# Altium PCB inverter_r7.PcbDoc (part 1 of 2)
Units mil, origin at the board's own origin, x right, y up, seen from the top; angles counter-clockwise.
Board outline 7000 x 5200 mil, 2 copper layers (Top Layer, Bottom Layer), stack 92.8 mil thick; 90 components, 75 nets, 259 pads, 1172 vias.
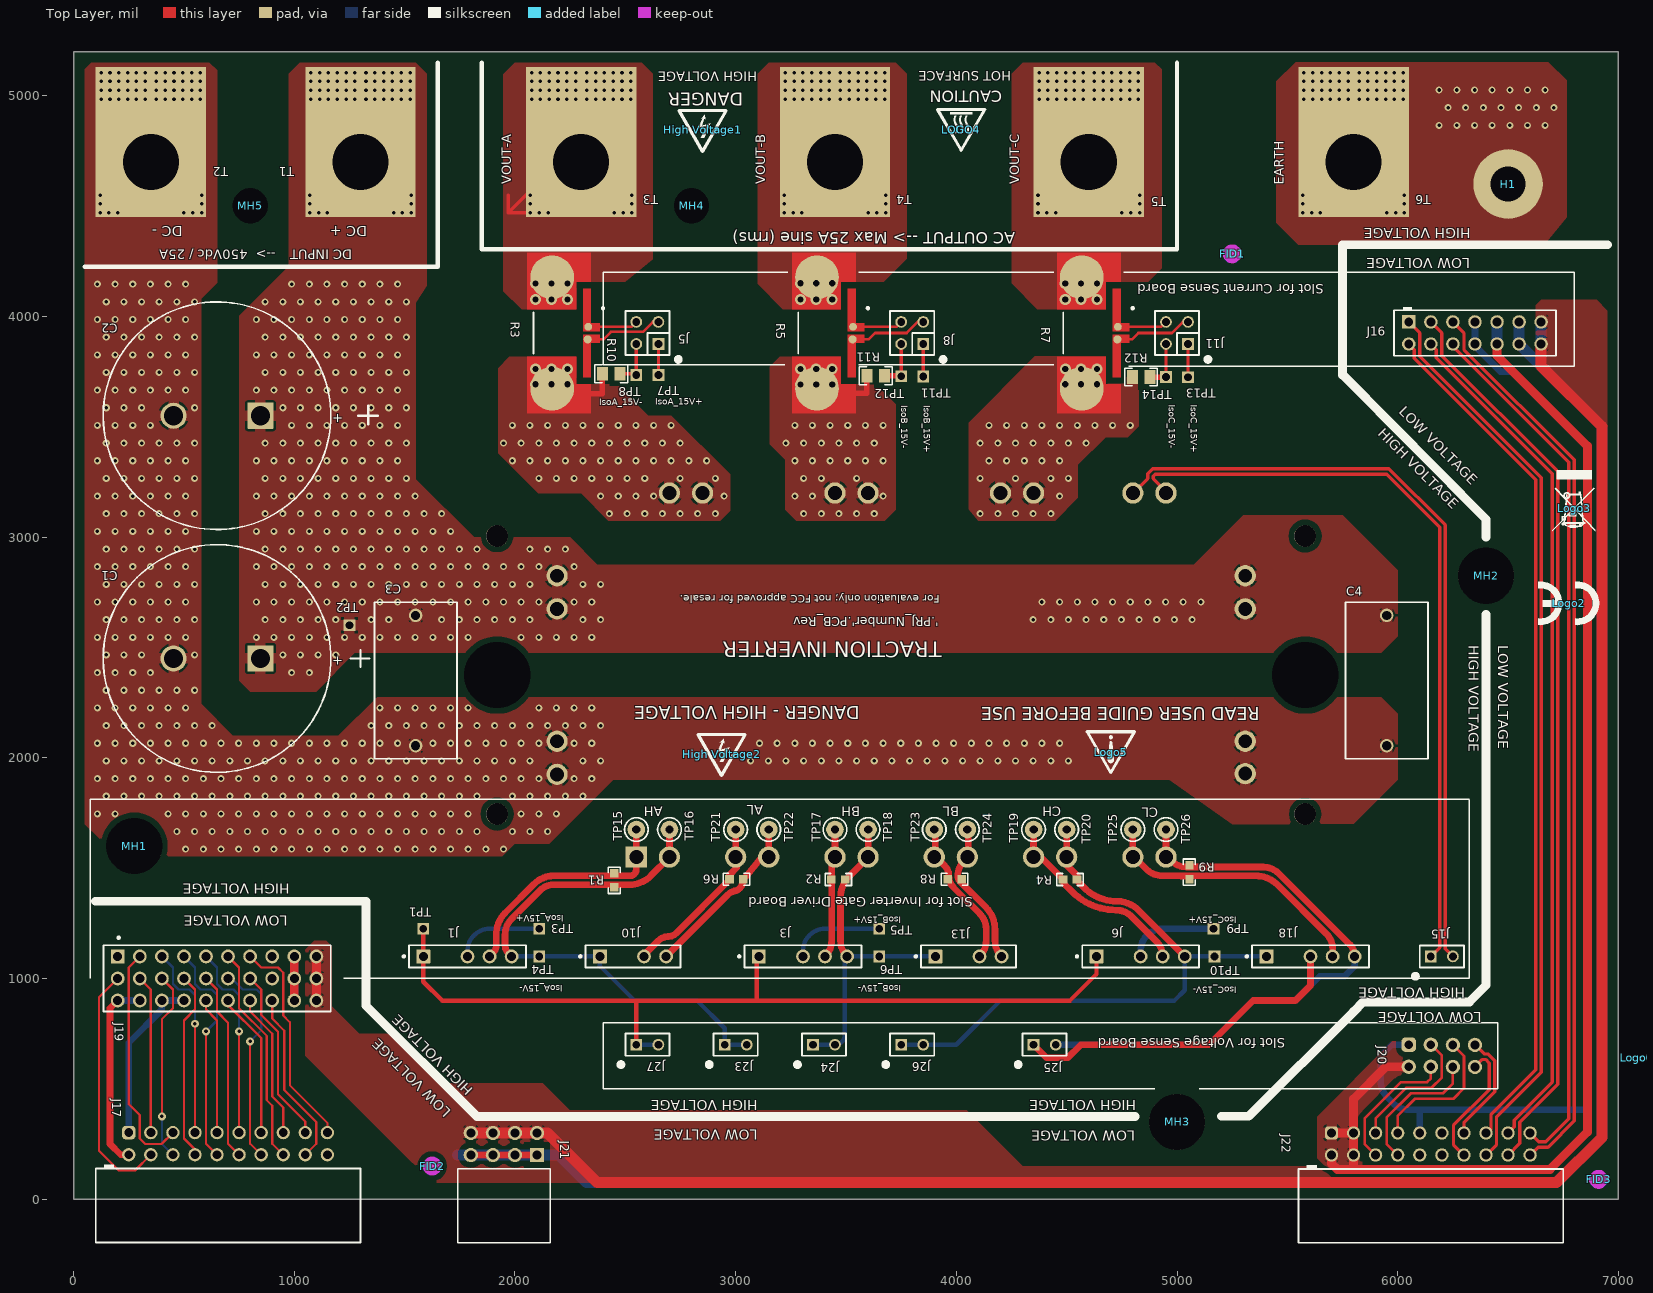
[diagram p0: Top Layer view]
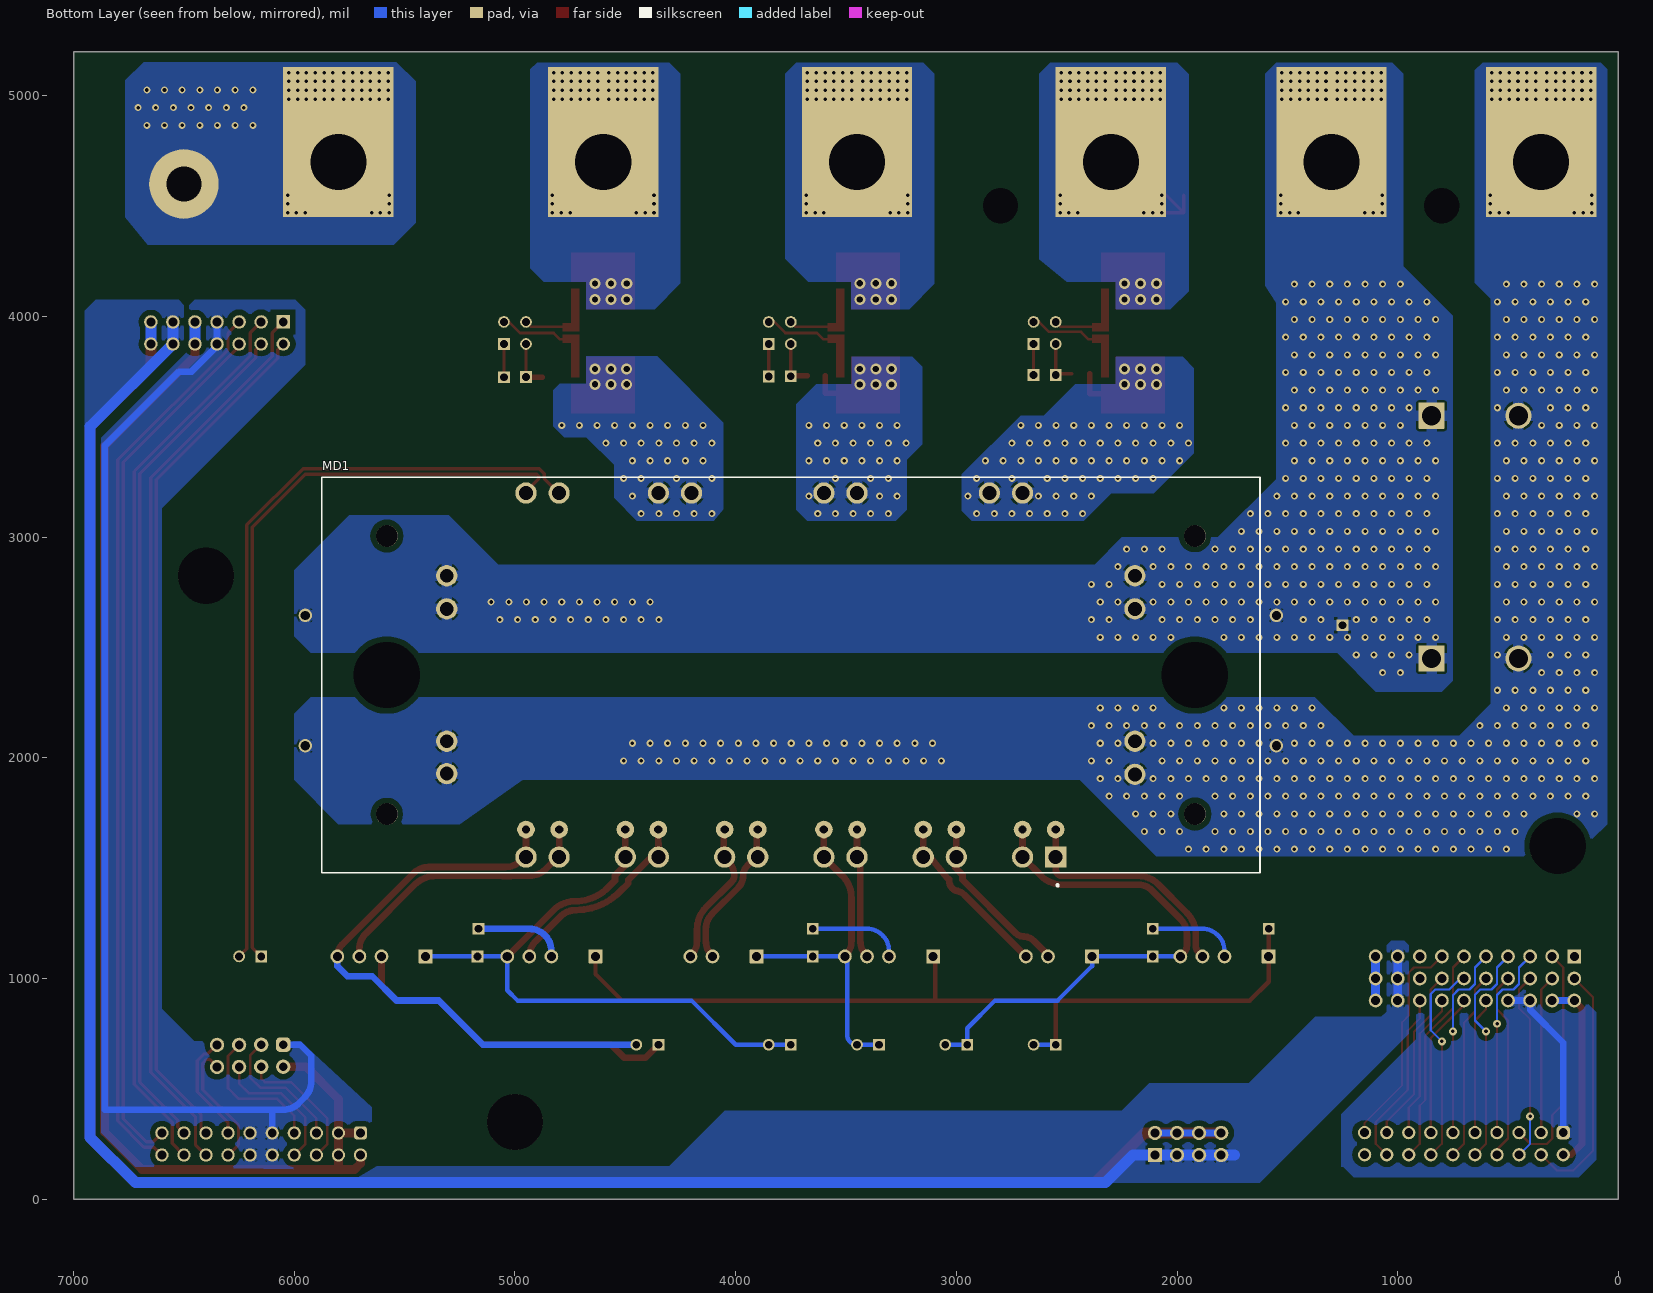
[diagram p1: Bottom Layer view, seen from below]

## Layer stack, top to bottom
Top Solder: solder mask 0.4, Solder Resist, Dk 3.5
Top Layer: signal copper 2.8
Dielectric1: core 87.2, FR-4, Dk 4.8
Bottom Layer: signal copper 2.8
Bottom Solder: solder mask 0.4, Solder Resist, Dk 3.5

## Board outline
0,0 7000,0 7000,5200 0,5200

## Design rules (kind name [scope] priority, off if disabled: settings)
AcuteAngle [All] p1: minimum=4.50000000000000E+0001 checktracksonly=FALSE
AssemblyTestPointUsage [All] p1: valid=2
BoardOutlineClearance BoardOutlineClearance_MountingHoles [OnCopper and InComponentClass('Mounting Holes')] p1: gap=39.37 ignorepadtopadclearanceinfootprint=FALSE
BoardOutlineClearance BoardOutlineClearance_Poly [OnCopper and IsPoly] p2: gap=25 ignorepadtopadclearanceinfootprint=FALSE
BoardOutlineClearance [OnCopper and Not InComponentClass('Logo') and not InComponentClass('FiducialMark') and not InRegion(1000,500,4000,800) and not InPoly] p3: gap=50 ignorepadtopadclearanceinfootprint=FALSE
Clearance Clearance_Keepouts [((IsTrack Or IsArc) And Not InPoly) And IsFree and IsKeepOut vs ((IsTrack Or IsArc) And Not InPoly) And IsFree and IsKeepOut] p1: gap=0 ignorepadtopadclearanceinfootprint=FALSE
Clearance Clearance_Poly [InPolygon] p2: gap=25 ignorepadtopadclearanceinfootprint=TRUE
Clearance Clearance_FiducialMark [IsKeepOut and InComponentClass('FiducialMark') vs IsPad and InComponentClass('FiducialMark')] p3: gap=0 ignorepadtopadclearanceinfootprint=FALSE
Clearance [All] p4: gap=10 ignorepadtopadclearanceinfootprint=TRUE
ComponentClearance ComponentClearance_MountingHoles_FiducialMarks [InComponentClass('Mounting Holes') vs InComponentClass('FiducialMark')] p1: gap=50 collisioncheckmode=3 verticalgap=10 showdistances=FALSE
ComponentClearance ComponentClearance_Shunt [InComponentClass('Header') vs InComponentClass('Shunt')] p2: gap=0 collisioncheckmode=3 verticalgap=0 showdistances=FALSE
ComponentClearance ComponentClearance_Logo [InComponentClass('Logo')] p3: gap=50 collisioncheckmode=3 verticalgap=10 showdistances=FALSE
ComponentClearance ComponentClearance_ScrewToNut [(HasFootprint('NY PMS 440 0025 PH')) vs (HasFootprint('Keystone_1902C'))] p4: gap=5 collisioncheckmode=3 verticalgap=10 showdistances=FALSE
ComponentClearance ComponentClearance_MountingHoles [InComponentClass('Mounting Holes')] p5: gap=250 collisioncheckmode=3 verticalgap=100000 showdistances=FALSE
ComponentClearance ComponentClearance_SmallPassives [HasFootprint('0201*') or HasFootprint('0402*') or HasFootprint('0508') or HasFootprint('0603*') or HasFootprint('0612') or HasFootprint('0805*') or HasFootprint('0815*') or HasFootprint('0830*') or HasFootprint('1206*') or HasFootprint('1210*') or HasFootprint('1808*') or HasFootprint('1812*') or HasFootprint('1825*') or HasFootprint('2010*') or HasFootprint('2220*') or HasFootprint('2225*') or HasFootprint('2512*') or HasFootprint('2728*') or HasFootprint('3518*') vs HasFootprint('0201*') or HasFootprint('0402*') or HasFootprint('0508') or HasFootprint('0603*') or HasFootprint('0612') or HasFootprint('0805*') or HasFootprint('0815*') or HasFootprint('0830*') or HasFootprint('1206*') or HasFootprint('1210*') or HasFootprint('1808*') or HasFootprint('1812*') or HasFootprint('1825*') or HasFootprint('2010*') or HasFootprint('2220*') or HasFootprint('2225*') or HasFootprint('2512*') or HasFootprint('2728*') or HasFootprint('3518*')] p6: gap=14.96 collisioncheckmode=3 verticalgap=10 showdistances=FALSE
ComponentClearance ComponentClearance_THtoSMT [IsThruComponent vs IsSMTComponent] p7: gap=40 collisioncheckmode=3 verticalgap=30 showdistances=FALSE
ComponentClearance ComponentClearance_THtoTH [IsThruComponent vs IsThruComponent] p8: gap=30 collisioncheckmode=3 verticalgap=30 showdistances=FALSE
ComponentClearance [All] p9: gap=30 collisioncheckmode=3 verticalgap=10 showdistances=FALSE
DiffPairsRouting [All] p1: maxlimit=100 minlimit=10 mostfreqgap=10 toplayer_minwidth=15 toplayer_maxwidth=30 toplayer_prefwidth=15 bottomlayer_minwidth=15 bottomlayer_maxwidth=30 bottomlayer_prefwidth=15 maxuncoupledlength=1000
FabricationTestPointUsage TestPointUsage [All] p1: valid=2 allowmultiple=FALSE
FabricationTestpoint Testpoint [All] p1: side=3 testpointundercomponent=TRUE minsize=40 maxsize=100 preferedsize=60 minholesize=0 maxholesize=40 preferedholesize=32 testpointgrid=1 allowsidetop=TRUE allowsidebottom=TRUE usegrid=TRUE gridtolerance=0.01
FanoutControl Fanout_LCC [IsLCC] p1: bgadir=Out bgaviamode=Centered fanoutstyle=Auto fanoutdirection=Alternating viagrid=1 // Fanout_LCC (Default Rule)
FanoutControl Fanout_BGA [IsBGA] p2: bgadir=Out bgaviamode=Centered fanoutstyle=Auto fanoutdirection=Alternating viagrid=1 // Fanout_BGA (Default Rule)
FanoutControl Fanout_Default [All] p4: bgadir=Out bgaviamode=Centered fanoutstyle=Auto fanoutdirection=Alternating viagrid=1 // Fanout_Default (Default Rule)
FanoutControl Fanout_Small [(CompPinCount < 5)] p5: bgadir=Out bgaviamode=Centered fanoutstyle=Auto fanoutdirection=OutThenIn viagrid=1 // Fanout_Small (Default Rule)
Height [All] p1: minheight=0 maxheight=2000 prefheight=500
HoleSize [All] p1: absolutevalues=TRUE maxlimit=320 minlimit=7.87 maxpercent=80.000 minpercent=20.000
MinimumAnnularRing MinimumAnnularRing_ThermalPadVias [IsVia and InAnyComponent] p1: minimumring=5.91
MinimumAnnularRing [All] p2: minimumring=7.87
MinimumSolderMaskSliver MinimumSolderMaskSliver_Logo [InComponentClass('Logo') vs InComponentClass('Logo')] p1: minsoldermaskwidth=0.7
MinimumSolderMaskSliver [All] p2: minsoldermaskwidth=3.94
PlaneConnect [All] p1: planeconnectstyle=Relief reliefexpansion=10 reliefentries=4 reliefconductorwidth=10 reliefairgap=10
PolygonConnect PolygonConnect_1 [InComponentClass('Terminal')   or InComponent('H1')] p1: connectstyle=Direct reliefconductorwidth=10 reliefentries=4 polygonreliefangle="90 Angle" airgapwidth=10
PolygonConnect PolygonConnect_stitching [IsVia And ((HoleSize = 16) Or (HoleSize = 28))] p2: connectstyle=Direct reliefconductorwidth=30 reliefentries=4 polygonreliefangle="90 Angle" airgapwidth=10
PolygonConnect [All] p3: connectstyle=Relief reliefconductorwidth=50 reliefentries=4 polygonreliefangle="90 Angle" airgapwidth=10
RoutingVias ThermalPadVias [IsVia and InAnyComponent and not InComponentClass('Terminal')] p1: holewidth=7.87 width=19.68 viastyle="Through Hole" minholewidth=7.87 minwidth=19.68 maxholewidth=12.99 maxwidth=23.62
RoutingVias [IsVia and InAnyComponent] p2: holewidth=16 width=34 viastyle="Through Hole" minholewidth=7.87 minwidth=26 maxholewidth=40 maxwidth=65
SilkToBoardRegionClearance [Not ((IsComment or IsDesignator) And (Hide <> 'False')) and not InRegion(1000,500,4000,800)] p1:
SilkToSilkClearance SilkToSilkClearance_Pb-FreeLogo [(HasFootprint('Pb-Free_Overlay_Medium') OR HasFootprint('Pb-Free_Overlay_Small')) vs (HasFootprint('Pb-Free_Overlay_Medium') OR HasFootprint('Pb-Free_Overlay_Small'))] p1: silktosilkclearance=0
SilkToSilkClearance [All] p2: silktosilkclearance=3.94
SilkToSolderMaskClearance SilkToComponentPadClearance [(IsPad or IsFill or IsRegion) and InAnycomponent] p1: minsilkscreentomaskgap=5 clearancetoexposedcopper=TRUE
SilkToSolderMaskClearance "Silk to Solder Mask Opening" [All] p2: minsilkscreentomaskgap=3.94 clearancetoexposedcopper=FALSE
SolderMaskExpansion [All] p1: expansion=1.97
UnRoutedNet [All] p1: checkbadconnections=TRUE
Width [All] p1: maxlimit=100 minlimit=6 preferedwidth=10 checkconnectedcopper=TRUE
13 further rules are at their usual default settings.

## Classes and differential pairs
component class Terminal: T1 T2 T3 T4 T5 T6
component class inverter_r5: C1 C2 C3 C4 H1 H9 J1 J3 J5 J6 J8 J10 J11 J13 J15 J16 J17 J18 J19 J20 J21 J22 J23 J24 J25 J26 J27 MD1 R1 R2 R3 R4 R5 R6 R7 R8 R9 R10 R11 R12 T1 T2 T3 T4 T5 T6 TP1 TP2 TP3 TP4 TP5 TP6 TP7 TP8 TP9 TP10 TP11 TP12 TP13 TP14 TP15 TP16 TP17 TP18 TP19 TP20 TP21 TP22 TP23 TP24 TP25 TP26
component class "Mounting Holes": H1 H9
component class Hardware: FID1 FID2 FID3 "High Voltage1" "High Voltage2" Logo2 Logo3 LOGO4 Logo5 Logo6 MH1 MH2 MH3 MH4 MH5 ZZ1 ZZ2 ZZ3 ZZ4
component class FiducialMark: FID1 FID2 FID3
component class AssemblyNote: ZZ1 ZZ2 ZZ3 ZZ4
differential pair HS: +HS_P -HS_N
differential pair Vdc: +Vdc_P -Vdc_N
differential pair Ic: +Ic_P -Ic_N
differential pair Ib: +Ib_P -Ib_N
differential pair Ia: +Ia_P -Ia_N

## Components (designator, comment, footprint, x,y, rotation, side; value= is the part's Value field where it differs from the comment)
C1 "LLS2W221MELA" Nichicon_2500x4000_Snap 650,2450 r180 top value=220uF
C2 "LLS2W221MELA" Nichicon_2500x4000_Snap 650,3550 r180 top value=220uF
C3 "450MPK105J" MPK_1800x950 1550,2350 r270 top value=1uF
C4 "450MPK105J" MPK_1800x950 5950,2350 r270 top value=1uF
FID1 "Fiducial" Fiducial10-20 5250,4283.61 r0 top
FID2 "Fiducial" Fiducial10-20 1625,150 r0 top
FID3 "Fiducial" Fiducial10-20 6910,90 r0 top
H1 "NY PMS 440 0025 PH" "NY PMS 440 0025 PH" 6500,4600 r0 top (schematic designator H2)
"High Voltage1" "DANGER HIGH VOLTAGE" IEC_HighVoltage_Small 2850,4845 r180 top
"High Voltage2" "DANGER HIGH VOLTAGE" IEC_HighVoltage_Small 2936,2017 r180 top
J1 "SSW-105-01-G-S-002" FP-SSW-105-01-G-S-002_HDR4-MFG 1785,1100 r0 top
J3 "SSW-105-01-G-S-002" FP-SSW-105-01-G-S-002_HDR4-MFG 3305,1100 r0 top
J5 "5-534206-2" CONN_534206-2 2600,3925 r0 top locked
J6 "SSW-105-01-G-S-002" FP-SSW-105-01-G-S-002_HDR4-MFG 4835,1100 r0 top
J8 "5-534206-2" CONN_534206-2 3800,3925 r0 top locked
J10 "SSW-104-01-G-S-002" FP-SSW-104-01-G-S-002_HDR4-MFG 2535,1100 r0 top
J11 "5-534206-2" CONN_534206-2 5000,3925 r0 top locked
J13 "SSW-104-01-G-S-002" FP-SSW-104-01-G-S-002_HDR4-MFG 4055,1100 r0 top
J15 "5-534206-1" CONN_534206-1 6200,1100 r0 top
J16 "PPPC072LFBN-RC" Sullins_xPxC072LFBN-RC 6350,3925 r0 top
J17 "SFH11-PBPC-D10-RA-BK" Sullins_SFH11-xxxC-D10-RA 700,251.52 r0 top
J18 "SSW-105-01-G-S-002" FP-SSW-105-01-G-S-002_HDR4-MFG 5605,1100 r0 top
J19 "SSW-110-21-L-T" FP-SSW-110-21-L-T_HDR30-MFG 650,1000 r180 top
J20 "PPPC042LFBN-RC" CONN_PPPC042LFBN-RC 6200,649.5 r180 top
J21 "PPPC042LJBN-RC" CONN_PPPC042LJBN-RC 2100,200 r0 top
J22 "SFH11-PBPC-D10-RA-BK" Sullins_SFH11-xxxC-D10-RA 6150,250 r0 top
J23 "5-534206-1" CONN_534206-1 3000,700 r0 top
J24 "5-534206-1" CONN_534206-1 3400,700 r0 top
J25 "5-534206-1" CONN_534206-1 4400,700 r0 top
J26 "5-534206-1" CONN_534206-1 3800,700 r0 top
J27 "5-534206-1" CONN_534206-1 2600,700 r0 top
Logo2 "CE Mark" CE_Mark_5mm 6775,2700 r180 top
Logo3 "WEEE logo" WEEE_Minimum 6800,3130 r180 top
LOGO4 "CAUTION HOT SURFACE" IEC_HotSurface_Small 4021.99,4845 r180 top
Logo5 "CAUTION.  READ USER GUIDE BEFORE USE" IEC_Caution_Small 4700,2025 r180 top
Logo6 "FCC disclaimer" FCC_disclaimer 7083,641 r90 top
MD1 "CCS050M12CM2" FP-CCS050M12CM2_PTH_MODULE_107MM5_45MM-MFG 3750,2375 r0 bottom
MH1 "MTG_NoPads" MTG_159mil#1 275,1600 r0 top
MH2 "MTG_NoPads" MTG_159mil#1 6400,2825 r0 top
MH3 "MTG_NoPads" MTG_159mil#1 5000,350 r0 top
MH4 "MTG_NoPads" MTG_159mil#2 2800,4500.77 r0 top
MH5 "MTG_NoPads" MTG_159mil#3 800,4500 r0 top
R1 "CRCW060310K0FKEA" 0603 2450,1445 r270 top value=10.0k
R2 "CRCW060310K0FKEA" 0603 3465,1448.5 r0 top value=10.0k
R3 "CSS4J-4026R-L500F" FP-CSS4J-4026R-L500F_4026-MFG 2220,3925 r270 top locked
R4 "CRCW060310K0FKEA" 0603 4515,1448.5 r0 top value=10.0k
R5 "CSS4J-4026R-L500F" FP-CSS4J-4026R-L500F_4026-MFG 3420,3925 r270 top locked
R6 "CRCW060310K0FKEA" 0603 3003.5,1450 r0 top value=10.0k
R7 "CSS4J-4026R-L500F" FP-CSS4J-4026R-L500F_4026-MFG 4620,3925 r270 top locked
R8 "CRCW060310K0FKEA" 0603 3992.5,1450 r0 top value=10.0k
R9 "CRCW060310K0FKEA" 0603 5056.25,1481.5 r90 top value=10.0k
R10 "ERJ-6GEY0R00V" 0805_HV 2436.5,3740 r0 top value=0
R11 "ERJ-6GEY0R00V" 0805_HV 3635,3730.95 r0 top value=0
R12 "ERJ-6GEY0R00V" 0805_HV 4837.28,3725 r0 top value=0
T1 "CB70-14-CY" CB70-14-CY 1300,4700 r270 top
T2 "CB70-14-CY" CB70-14-CY 350,4700 r270 top
T3 "CB70-14-CY" CB70-14-CY 2300,4700 r270 top
T4 "CB70-14-CY" CB70-14-CY 3450,4700 r270 top
T5 "CB70-14-CY" CB70-14-CY 4600,4700 r270 top
T6 "CB70-14-CY" CB70-14-CY 5800,4700 r270 top
TP1 "TP_H0.45P0.75" TP_H045P075 1585,1225 r90 top
TP2 "TP_H0.45P0.75" TP_H045P075 1250,2600 r90 top
TP3 "TP_H0.45P0.75" TP_H045P075 2110,1225 r90 top
TP4 "TP_H0.45P0.75" TP_H045P075 2110,1100 r90 top
TP5 "TP_H0.45P0.75" TP_H045P075 3650.5,1225 r90 top
TP6 "TP_H0.45P0.75" TP_H045P075 3650.5,1100 r90 top
TP7 "TP_H0.45P0.75" TP_H045P075 2650,3735 r0 top
TP8 "TP_H0.45P0.75" TP_H045P075 2550,3735 r0 top
TP9 "TP_H0.45P0.75" TP_H045P075 5165.08,1225 r90 top
TP10 "TP_H0.45P0.75" TP_H045P075 5170,1100 r90 top
TP11 "TP_H0.45P0.75" TP_H045P075 3850,3728.13 r0 top
TP12 "TP_H0.45P0.75" TP_H045P075 3750,3728.52 r0 top
TP13 "TP_H0.45P0.75" TP_H045P075 5050,3724.21 r0 top
TP14 "TP_H0.45P0.75" TP_H045P075 4950,3725 r0 top
TP15 "TESTPOINT" TESTPOINT 2550,1675 r0 top
TP16 "TESTPOINT" TESTPOINT 2700,1675 r0 top
TP17 "TESTPOINT" TESTPOINT 3450,1675 r0 top
TP18 "TESTPOINT" TESTPOINT 3600,1675 r0 top
TP19 "TESTPOINT" TESTPOINT 4350,1675 r0 top
TP20 "TESTPOINT" TESTPOINT 4500,1675 r0 top
TP21 "TESTPOINT" TESTPOINT 3000,1675 r0 top
TP22 "TESTPOINT" TESTPOINT 3150,1675 r0 top
TP23 "TESTPOINT" TESTPOINT 3900,1675 r0 top
TP24 "TESTPOINT" TESTPOINT 4050,1675 r0 top
TP25 "TESTPOINT" TESTPOINT 4800,1675 r0 top
TP26 "TESTPOINT" TESTPOINT 4950,1675 r0 top
ZZ1 "This Assembly Note is for PCB labels only" AssemblyNoteLabel 385,7238 r0 top
ZZ2 "These assemblies are ESD sensitive, ESD precautions shall be observed." AssemblyNote 385,7129.11 r0 top
ZZ3 "These assemblies must be clean and free from flux and all contaminants. Use of no clean flux is not acceptable." AssemblyNote 385,7040.56 r0 top
ZZ4 "These assemblies must comply with workmanship standards IPC-A-610 Class 2, unless otherwise specified." AssemblyNote 385,6952 r0 top

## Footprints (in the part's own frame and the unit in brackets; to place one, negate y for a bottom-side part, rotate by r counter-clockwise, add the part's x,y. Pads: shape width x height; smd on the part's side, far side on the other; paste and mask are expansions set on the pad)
0603 [mm] "0603 from SM-752 data"
  rect 1x0.95 smd: 1(-0.8,0) 2(0.8,0)
  silkscreen extent -1.52,-0.69 1.52,0.69, body extent -0.87,-0.47 0.87,0.47, height 1
0805_HV [mil] "0805 with 30mil clearance between pads"
  rect 50x63 smd: 1(-40,0) 2(40,0)
  silkscreen extent -74,-40 74,40, body extent -43,-29 43,29, height 57
AssemblyNote [mil] "Assembly Note"
AssemblyNoteLabel [mil] "Assembly Note for PCB Labels"
CB70-14-CY [mil] "Terminal 90A Lug"
  rect 680x500 hole 254 copper offset -90,0 paste-250: 1(0,0)
  body extent -1300,-260 250,260, height 714
CE_Mark_5mm [mil] "Minimum text height for CE Mark"
  silkscreen extent -138,-98 138,98
CONN_534206-1 [mm] "TE_CONNECTIVITY"
  rect 1.35x1.35 hole 0.89: 1(-1.27,0)
  round 1.35 hole 0.89: 2(1.27,0)
  silkscreen extent -3.3,-2.54 2.54,1.27, body extent -2.51,-1.27 2.51,1.27, height 8.65
CONN_534206-2 [mm] "TE_CONNECTIVITY"
  rect 1.35x1.35 hole 0.89: 1(1.27,-1.27)
  round 1.35 hole 0.89: 2(1.27,1.27) 3(-1.27,-1.27) 4(-1.27,1.27)
  silkscreen extent -2.54,-3.3 3.81,2.54, body extent -2.54,-2.51 2.54,2.51, height 8.65
CONN_PPPC042LFBN-RC [mm] "Sullins socket, 100 mil spacing, 4x2"
  rrect50% 1.65x1.65 hole 1 mask+0: 1(3.81,-1.283)
  round 1.65 hole 1 mask+0: 2(3.81,1.257) 3(1.27,-1.283) 4(1.27,1.257) 5(-1.27,-1.257) 6(-1.27,1.283) 7(-3.81,-1.257) 8(-3.81,1.283)
  body extent -5.33,-2.55 5.33,2.53, height 8.52
CONN_PPPC042LJBN-RC [mm] "Sullins Right Angle Header"
  rect 1.65x1.65 hole 1.02 mask+0: 1(0,0)
  round 1.65 hole 1.02 mask+0: 2(0,2.54) 3(-2.54,0) 4(-2.54,2.54) 5(-5.08,0) 6(-5.08,2.54) 7(-7.62,0) 8(-7.62,2.54)
  silkscreen extent -9.14,-10.11 1.52,-1.6, body extent -9.14,-10.11 1.52,2.84, height 5.1
FCC_disclaimer [mil]
Fiducial10-20 [mm]
  round 1 smd mask+0.5: 1(0,0)
  Top Layer keep-out circle w1.178: c0,0 r0.5
FP-CCS050M12CM2_PTH_MODULE_107MM5_45MM-MFG [mm]
  rrect4% 2.45x2.45 hole 1.6 paste-1000 mask+0: 1(-30.48,20.95)
  round 2.45 hole 1.6 paste-1000 mask+0: 2(-26.67,20.95) 3(-19.05,20.95) 4(-15.24,20.95) 5(-7.62,20.95) 6(-3.81,20.95) 7(3.81,20.95) 8(7.62,20.95) 9(15.24,20.95) 10(19.05,20.95) 11(26.67,20.95) 12(30.48,20.95) 13(39.6,11.355) 14(39.6,7.62) 15(39.6,-7.62) 16(39.6,-11.43) 17(30.48,-20.95) 18(26.67,-20.95) 19(15.24,-20.95) 20(11.43,-20.95) 21(-3.81,-20.95) 22(-7.62,-20.95) 23(-22.86,-20.95) 24(-26.67,-20.95) 25(-39.6,-11.43) 26(-39.6,-7.62) 27(-39.6,7.62) 28(-39.6,11.43)
  round 2.5 hole 2.5 unplated paste-1000 mask+0: ""(-46.5,-16) ""(-46.5,16) ""(46.5,-16) ""(46.5,16)
  round 6.401 hole 7.645 unplated paste-1000 mask+0: ""(-46.5,0) ""(46.5,0)
  silkscreen extent -54,-22.75 54,24.32, body extent -53.75,-22.5 53.75,22.5, height 17.5
FP-CSS4J-4026R-L500F_4026-MFG [mil]
  round 35.35 smd paste+0 mask+0: 1(-27.81,111.96)
  round 36.64 smd paste+0 mask+0: 2(28.91,109.62)
  round 198.59 smd paste+0 mask+0: 3(-252.21,-51.43) 4(252.21,-51.43)
  Top Layer region: -364.17,-163.39 -108.27,-163.39 -108.27,57.09 -232.28,57.09 -232.28,124.02 -364.17,124.02 -364.17,-163.39
  Top Layer region: 364.17,-163.39 108.27,-163.39 108.27,57.09 232.28,57.09 232.28,124.02 364.17,124.02 364.17,-163.39
  Top Layer region: 7.87,88.58 200.79,88.58 200.79,124.02 43.31,124.02 43.31,163.39 7.87,163.39 7.87,88.58
  Top Layer region: -7.87,88.58 -200.79,88.58 -200.79,124.02 -43.31,124.02 -43.31,163.39 -7.87,163.39 -7.87,88.58
  silkscreen extent -117,-136 94,184, body extent -368,-167 368,167, height 10
FP-SSW-104-01-G-S-002_HDR4-MFG [mm]
  rrect6% 1.59x1.59 hole 1.04 paste-1000 mask+0: 1(-3.81,0)
  round 1.59 hole 1.04 paste-1000 mask+0: 3(1.27,0) 4(3.81,0)
  silkscreen extent -6.18,-1.27 5.46,1.27, body extent -5.56,-1.37 5.56,1.37, height 0.25
FP-SSW-105-01-G-S-002_HDR4-MFG [mm]
  rrect6% 1.59x1.59 hole 1.04 paste-1000 mask+0: 1(-5.08,0)
  round 1.59 hole 1.04 paste-1000 mask+0: 3(0,0) 4(2.54,0) 5(5.08,0)
  silkscreen extent -7.45,-1.27 6.73,1.27, body extent -6.83,-1.37 6.83,1.37, height 0.25
FP-SSW-110-21-L-T_HDR30-MFG [mm]
  rrect6% 1.59x1.59 hole 1.04 paste-1000 mask+0: 1(11.43,-2.54)
  round 1.59 hole 1.04 paste-1000 mask+0: 2(11.43,0) 3(11.43,2.54) 4(8.89,-2.54) 5(8.89,0) 6(8.89,2.54) 7(6.35,-2.54) 8(6.35,0) 9(6.35,2.54) 10(3.81,-2.54) 11(3.81,0) 12(3.81,2.54) 13(1.27,-2.54) 14(1.27,0) 15(1.27,2.54) 16(-1.27,-2.54) 17(-1.27,0) 18(-1.27,2.54) 19(-3.81,-2.54) 20(-3.81,0) 21(-3.81,2.54) 22(-6.35,-2.54) 23(-6.35,0) 24(-6.35,2.54) 25(-8.89,-2.54) 26(-8.89,0) 27(-8.89,2.54) 28(-11.43,-2.54) 29(-11.43,0) 30(-11.43,2.54)
  silkscreen extent -13.08,-4.81 13.08,3.81, body extent -13.18,-3.91 13.18,3.91, height 0.25
IEC_Caution_Small [mil]
  silkscreen extent -107,-93 107,92
IEC_HighVoltage_Small [mil]
  silkscreen extent -107,-88 107,97
IEC_HotSurface_Small [mil]
  silkscreen extent -107,-93 107,92
MPK_1800x950 [mm] "TH, 2-Leads, Body 18x9.5mm, Lead Spacing 15mm"
  round 1.55 hole 1.05: 1(-7.5,0) 2(7.5,0)
  silkscreen extent -9,-4.75 9,4.75, body extent -9,-4.75 9,4.75, height 14
MTG_159mil#1 [mil] "159mil Non Plated Hole"
  round 250 hole 254 unplated: 1(0,0)
MTG_159mil#2 [mil] "159mil Non Plated Hole"
  round 150 hole 160 unplated: 1(0,0)
MTG_159mil#3 [mil] "159mil Non Plated Hole"
  round 150 hole 160 unplated: 1(0,0.77)
Nichicon_2500x4000_Snap [mm]
  rrect3% 3x3 hole 2.2: 1(-5,0)
  round 3 hole 2.2: 2(5,0)
  silkscreen extent -13.1,-13.1 13.1,13.1, body extent -13,-13 13.01,13, height 42.01
"NY PMS 440 0025 PH" [mm] "4-40 nylon screw and mounting hole"
  round 8 hole 4.064: 1(0,0)
  body extent -3.3,-3.3 3.3,3.3, height 2.69
Sullins_SFH11-xxxC-D10-RA [mm] "Receptacle, 2.54mm, 10x2, R/A, TH"
  rrect50% 1.53x1.53 hole 1.02: 1(-11.43,1.27)
  round 1.53 hole 1.02: 2(-11.43,-1.27) 3(-8.89,1.27) 4(-8.89,-1.27) 5(-6.35,1.27) 6(-6.35,-1.27) 7(-3.81,1.27) 8(-3.81,-1.27) 9(-1.27,1.27) 10(-1.27,-1.27) 11(1.27,1.27) 12(1.27,-1.27) 13(3.81,1.27) 14(3.81,-1.27) 15(6.35,1.27) 16(6.35,-1.27) 17(8.89,1.27) 18(8.89,-1.27) 19(11.43,1.27) 20(11.43,-1.27)
  silkscreen extent -15.24,-11.37 15.24,-2.4, body extent -15.24,-11.37 15.24,1.47, height 7
Sullins_xPxC072LFBN-RC [mm] "Receptacle, 2.54mm, 7x2, TH"
  rect 1.55x1.55 hole 1.02: 1(-7.62,1.27)
  round 1.55 hole 1.02: 2(-7.62,-1.27) 3(-5.08,1.27) 4(-5.08,-1.27) 5(-2.54,1.27) 6(-2.54,-1.27) 7(0,1.27) 8(0,-1.27) 9(2.54,1.27) 10(2.54,-1.27) 11(5.08,1.27) 12(5.08,-1.27) 13(7.62,1.27) 14(7.62,-1.27)
  silkscreen extent -9.31,-2.61 9.31,3, body extent -9.31,-2.61 9.31,2.61, height 8.65
TESTPOINT [mil]
  round 80 hole 37.99: 1(0,0)
  silkscreen extent -54,-53 54,53
TP_H045P075 [mm] "TP_H0.45P0.75"
  rect 1.35x1.35 hole 0.89: 1(0,0)
WEEE_Minimum [mil] "WEEElie bin"
  silkscreen extent -95,-172 99,104

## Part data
C1 C2: library part CMP-0010109-2, "CAP, AL, 220 uF, 450 V, +/- 20%, TH", Cap_Case=25x40mm, Manufacturer=Nichicon, Supplier Part Number 1=493-2610-ND, Tolerance_%=20%, Value1=Unknown, Value2=450V, ValueDisplayed=220uF
C3 C4: library part CMP-0012307-1, "CAP, Film, 1 uF, 450 V, +/- 5%, TH", Cap_Case=18x9.5mm, Manufacturer=Rubycon, Supplier Part Number 1=1189-1822-ND, Tolerance_%=5%, Value1=Unknown, Value2=450V, ValueDisplayed=1uF
FID1 FID2 FID3: library part CMP-0077181-1, "Fiducial mark.  There is nothing to buy or mount.", Manufacturer=N/A
H1: library part CMP-0003617-1, "Machine Screw, Round, #4-40 x 1/4, Nylon, Philips panhead", Manufacturer="B&F Fastener Supply", Supplier Part Number 1=H542-ND
"High Voltage1" "High Voltage2": library part CMP-0074835-1, "IEC 61010-1 High Voltage Warning"
J1 J3 J6 J18: library part CMP-0088431-1, "Conn Socket Strip SKT 5 POS 2.54mm Solder ST Thru-Hole", Current_A=4.7A, Digikey Part Number=SSW-105-01-G-S-002-ND, Manufacturer=Samtec, Mouser Part Number=200-SSW10501GS002, Operating Temperature Range="-55°C to +125°C", Voltage_V=655V
J5 J8 J11: library part CMP-0054835-1, "Connector, Receptacle, 100mil, 2x2, Gold plated, TH", Manufacturer="TE Connectivity", Supplier Part Number 1=A32933-ND
J10 J13: library part CMP-0088428-1, "4 Position Receptacle Connector Through Hole", Current_A=4.7A, Digikey Part Number=SSW-104-01-G-S-002-ND, Manufacturer=Samtec, Operating Temperature Range="-55°C to +125°C", Voltage_V=655V
J15 J23 J24 J25 J26 J27: library part CMP-0054836-1, "Connector, Receptacle, 100mil, 2x1, Gold plated, TH", Manufacturer="TE Connectivity", Supplier Part Number 1=A32932-ND
J16: library part CMP-0054669-1, "Receptacle, 2.54mm, 7x2, Gold, TH", Color=Black, Manufacturer="Sullins Connector Solutions", Supplier Part Number 1=S7110-ND
J17 J22: library part CMP-0074634-1, "Receptacle, 2.54mm, 10x2, Gold, R/A, TH", Color=Black, Current_A=3A, Manufacturer="Sullins Connector Solutions", Supplier Part Number 1=S9205-ND, Voltage_V=1kV
J19: library part CMP-0088699-1, "Connector, Header, 30 Position Receptacle, Through Hole", Current_A=4.7A, Digikey Part Number=SSW-110-21-L-T-ND, Manufacturer=Samtec, Operating Temperature Range="-55°C to +125°C", Voltage_V=655V
J20: library part CMP-0054629-2, "Connector, Receptacle, 100mil, 4x2, Gold plated, TH", Manufacturer="Sullins Connector Solutions", Supplier Part Number 1=S7107-ND
J21: library part CMP-0054630-1, "Connector, Receptacle, 100mil, 4x2, Gold plated, R/A, TH", Manufacturer="Sullins Connector Solutions", Supplier Part Number 1=S5557-ND
Logo2: library part CMP-0074844-1
Logo3: library part CMP-0074769-1
LOGO4: library part CMP-0074837-1, "IEC 61010-1 Hot Surface Warning"
Logo5: library part CMP-0074836-1, "IEC 61010-1 Caution Warning"
Logo6: library part CMP-0074847-1, "FCC_disclaimer"
MD1: library part CMP-0087815-2, "Mosfet Array 6 N-Channel (3-Phase Bridge) 1200V (1.2kV) 87A (Tc) 337W Chassis Mount Module", Manufacturer=Wolfspeed
MH1 MH2 MH3 MH4 MH5: library part CMP-0078424-2, "PCB Mounting Hole, No Pad", Manufacturer=Any, PartNumber=N/A
R1 R2 R4 R6 R8 R9: library part CMP-0021998-4, "RES, 10.0 k, 1%, 0.1 W, AEC-Q200 Grade 0, 0603", Manufacturer=Vishay-Dale, Power_W=100mW, Supplier Part Number 1=541-10.0KHCT-ND, TempCo="100 ppm/C", Tolerance_%=1%, Value2=0.1W, Value_Code=10k0, ValueDisplayed=10.0k
R3 R5 R7: library part CMP-0087828-1, "RES SMD 500 UOHM 1% 5W 4026", Manufacturer=Bourns, Power_W=5W, TempCo=100ppm/°C, Tolerance_%=1%
R10 R11 R12: library part CMP-0020616-3, "RES, 0, 5%, 0.125 W, AEC-Q200 Grade 0, 0805", Manufacturer=Panasonic, Power_W=125mW, Supplier Part Number 1=P0.0ACT-ND, TempCo="600 ppm/C", Tolerance_%=5%, Value2=0.125W, Value_Code=0000, ValueDisplayed=0
T1 T2 T3 T4 T5 T6: library part CMP-0055443-2, "Terminal 90A Lug", Manufacturer=Panduit, Supplier Part Number 1=CB70-14-CY-ND, Voltage_V=600V
TP1 TP2 TP3 TP4 TP5 TP6 TP7 TP8 TP9 TP10 TP11 TP12 TP13 TP14: library part CMP-0003719-1, "Testpoint", Manufacturer="Texas Instruments"
TP15 TP16 TP17 TP18 TP19 TP20 TP21 TP22 TP23 TP24 TP25 TP26: library part CMP-0078143-3, "TEST POINT.  No entry in BOM.", Manufacturer=N/A
ZZ1: library part CMP-0003616-3
ZZ2: library part CMP-0077236-1
ZZ3: library part CMP-0077237-1
ZZ4: library part CMP-0077238-1

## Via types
v1: diameter 32, hole 16, Top Layer to Bottom Layer, tented both sides, 762 vias
v2: diameter 32, hole 16, Top Layer to Bottom Layer, 369 vias
v3: diameter 50, hole 28, Top Layer to Bottom Layer, 36 vias
v4: diameter 36, hole 16, Top Layer to Bottom Layer, 5 vias

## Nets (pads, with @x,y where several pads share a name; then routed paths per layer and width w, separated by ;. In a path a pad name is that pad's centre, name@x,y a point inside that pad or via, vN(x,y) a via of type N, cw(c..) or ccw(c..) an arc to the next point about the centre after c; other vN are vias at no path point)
5V: J16.13 J16.14 J19.28 J19.29 J19.30 J21.2 J21.4 J21.6 J21.8 | length 9812
  Top Layer w40: J19.30@1100,900 J19.29@1100,1000 J19.28@1100,1100
  Top Layer w50: J21.8@1800,300 J21.6@1900,300 J21.4@2000,300 J21.2@2100,300 2146.72,300 2371.72,75 6720,75 6925,280 6925,3500 6650,3775 J16.14@6650,3875
  Bottom Layer w30: J21.8@1800,300 J21.6@1900,300 J21.4@2000,300 J21.2@2100,300
  Bottom Layer w40: J19.30@1100,900 J19.29@1100,1000 J19.28@1100,1100
  Bottom Layer w50: J16.14@6650,3875 J16.13@6650,3975
5V_GND: J16.11 J16.12 J19.25 J19.26 J19.27 J21.1 J21.3 J21.5 J21.7 | length 9873
  Top Layer w30: J21.7@1800,200 J21.5@1900,200 J21.3@2000,200 J21.1@2100,200
  Top Layer w40: J19.27@1000,900 J19.26@1000,1000 J19.25@1000,1100
  Bottom Layer w40: J19.27@1000,900 J19.26@1000,1000 J19.25@1000,1100
  Bottom Layer w50: 1739.02,200 J21.7@1800,200 J21.5@1900,200 J21.3@2000,200 J21.1@2100,200 2200,200 2325,75 6720,75 6925,280 6925,295.66 6925,3500 J16.12@6550,3875 J16.11@6550,3975
15V_HS_A: J1.3 TP3.1 | length 407.1
  Bottom Layer w20: J1.3@1785,1100 1785,1125 cw(c1885,1125) 1885,1225 TP3.1@2110,1225
15V_HS_B: J3.3 TP5.1 | length 427.6
  Bottom Layer w20: J3.3@3305,1100 3305,1125 cw(c3405,1125) 3405,1225 TP5.1@3650.5,1225
15V_HS_C: J6.3 TP9.1 | length 412.2
  Bottom Layer w30: J6.3@4835,1100 4835,1125 cw(c4935,1125) 4935,1225 TP9.1@5165.08,1225
15V_LS: J18.3 J25.1 | length 1547.7
  Top Layer w30: J25.1@4350,700 4410,640 4504.13,640 4564.14,700 5145,700 5345,900 5537.01,900 5605,967.99 J18.3@5605,1100
+3V3: J16.9 J16.10 J20.2 J22.1 J22.2 J22.3 J22.4 | length 5848.2
  Top Layer w40: J22.2@5700,200 5700,161.81 5726.81,135 5800,135 ; J22.1@5700,300 J22.3@5800,300 ; J20.2@6050,600 5946.29,600 5800,453.71 J22.3@5800,300 ; J16.10@6450,3875 6450,3822.05 6859.22,3412.83 6859.22,304.22 6690,135 5800,135 ; 5800,135 J22.4@5800,200 J22.3@5800,300
  Bottom Layer w50: J16.10@6450,3875 J16.9@6450,3975
AGND: J16.7 J16.8 J20.1 J22.9 J22.10 J22.11 J22.12 | length 5188.3
  Bottom Layer w30: J20.1@6050,700 5973.2,700 5923.2,650 5923.2,532.61 ccw(c6023.2,532.61) 5952.49,461.9 5980.1,434.29 ccw(c6050.81,505) 6050.81,405 6100,405 ; J22.9@6100,300 6100,405 ; J16.7@6350,3975 J16.8@6350,3875 6350,3865.76 6465.76,3750 6522.05,3750 6859.22,3412.83 6859.22,405 6100,405
AH_N: J1.5 J10.1 J23.1 J23.2 MD1.2 R1.2 TP4.1 TP16.1 | length 2435.7
  Top Layer w30: J1.5@1985,1100 1969.14,1115.86 cw(c2003.28,1150) 1955,1150 1955,1198.58 cw(c2055,1198.58) 1984.29,1269.29 2115.25,1400.25 cw(c2175,1340.5) 2175,1425 2517.94,1425 ccw(c2517.94,1565) 2616.84,1465.91 ; 2616.94,1466.01 cw(c2517.94,1565) 2616.84,1465.91 ; TP16.1@2700,1675 MD1.2@2700,1550.2 2700,1549.07 2616.84,1465.91
  Bottom Layer w20: J1.5@1985,1100 TP4.1@2110,1100 J10.1@2385,1100 2385,1056.35 2541.35,900 2825,900 2950,775 J23.1@2950,700 J23.2@3050,700
AH_P: J1.4 MD1.1 R1.1 TP15.1 | length 1061.2
  Top Layer w30: J1.4@1885,1100 1900.86,1115.86 ccw(c1866.72,1150) 1915,1150 1915,1198.58 cw(c2055,1198.58) 1956.01,1297.57 2086.97,1428.54 cw(c2175,1340.5) 2175,1465 2518,1465 ; 2521,1465.2 ccw(c2521,1493.51) 2549.25,1495.39 ; 2550,1495 MD1.1@2550,1550.2 ; MD1.1@2550,1560.2 2550,1630.39 TP15.1@2550,1675
AL_N: J10.4 MD1.4 R6.2 TP22.1 | length 803.1
  Top Layer w30: J10.4@2685,1100 2965,1380 cw(c3009.17,1335.83) 3001.77,1397.86 ccw(c2984.22,1442.84) R6.2@3032.03,1449.58 ; R6.2@3042.48,1456.78 3122.17,1552.97 MD1.4@3150,1552.97 ; MD1.4@3126.93,1541.93 cw(c3154.13,1514.74) MD1.4@3150,1552.97 ; TP22.1@3150,1675 MD1.4@3150,1552.97
AL_P: J10.3 MD1.3 R6.1 TP21.1 | length 842.4
  Top Layer w30: J10.3@2585,1100 2585,1105.87 2650.83,1171.7 cw(c2695,1127.53) 2695,1190 ccw(c2695,1238.28) 2729.14,1204.14 R6.1@2973.5,1448.5 ; R6.1@2972.01,1450 2972.01,1469.49 3004.13,1501.61 MD1.3@3004.13,1553.2 ; TP21.1@3000,1675 MD1.3@3000,1550.2 3003,1553.2 MD1.3@3004.13,1553.2 ; MD1.3@3015.46,1531.89 3015.46,1564.54 MD1.3@3015.1,1564.17 ; MD1.3@3004.13,1553.2 MD1.3@3015.1,1564.17 ; MD1.3@3004.13,1553.2 MD1.3@3015.1,1564.17
ASC_EN: J17.3 J19.5 | length 719.2
  Top Layer w10: J19.5@300,1000 350,950 J17.3@350,301.52
ASC_H: J17.5 J19.4 | length 1048.6
  Top Layer w10: J19.4@300,1100 250,1050 250,431.19 300,381.19 300,274.66 325,249.66 398.15,249.66 J17.5@450,301.52
ASC_L: J17.7 J19.7 | length 889.9
  Top Layer w10: J17.7@550,301.52 v4(550,795)
  Bottom Layer w10: J19.7@400,1100 450,1050 450,975 475,950 525,950 550,925 v4(550,795)
BH_N: J3.5 J13.1 J24.1 J24.2 MD1.6 R2.2 TP6.1 TP18.1 | length 1563.4
  Top Layer w30: J3.5@3505,1100 3504.29,1100.71 cw(c3575,1171.42) 3475,1171.42 3475,1366.08 cw(c3615,1366.08) 3516.01,1465.08 MD1.6@3604.13,1553.2 ; MD1.6@3600,1550.2 TP18.1@3600,1675
  Bottom Layer w20: J24.1@3350,700 J24.2@3450,700 ccw(c3450,745) 3495,745 3495,1090 J3.5@3505,1100 TP6.1@3650.5,1100 J13.1@3905,1100
BH_P: J3.4 MD1.5 R2.1 TP17.1 | length 591.2
  Top Layer w30: J3.4@3405,1100 3405.71,1100.71 ccw(c3335,1171.42) 3435,1171.42 3435,1507.02 cw(c3500.3,1507.02) MD1.5@3454.13,1553.2 ; MD1.5@3450,1550.2 TP17.1@3450,1675
BL_N: J13.4 MD1.8 R8.2 TP24.1 | length 635.8
  Top Layer w30: TP24.1@4054.65,1649.73 4054.13,1553.2 4034.9,1533.97 ccw(c4103.86,1465) 4006.33,1465 ccw(c4041.97,1465) 4016.77,1439.8 4133.99,1322.57 cw(c4035,1223.58) 4175,1223.58 4175,1171.42 ccw(c4275,1171.42) 4204.29,1100.71 J13.4@4205,1100
BL_P: J13.3 MD1.7 R8.1 TP23.1 | length 643.6
  Top Layer w30: TP23.1@3904.53,1650.15 3904.13,1553.2 3947.95,1509.37 cw(c3903.58,1465) 3966.33,1465 ccw(c4041.97,1465) 3988.48,1411.52 4105.71,1294.29 cw(c4035,1223.58) 4135,1223.58 4135,1171.42 cw(c4035,1171.42) 4105.71,1100.71 J13.3@4105,1100
CH_N: J6.5 J18.1 J26.1 J26.2 MD1.10 R4.2 TP10.1 TP20.1 | length 2834.3
  Top Layer w30: MD1.10@4500,1550.2 MD1.10@4503.56,1553.76 ; TP20.1@4500,1675 4499.53,1557.79 MD1.10@4503.56,1553.76 ; MD1.10@4504.13,1515.39 4504.13,1553.2 MD1.10@4503.56,1553.76 ; 4743.58,1350 4727.01,1350 ; J6.5@5035,1100 4826.01,1308.99 ccw(c4727.01,1210) 4727.01,1350 ; J6.5@5035,1110 J6.5@5040,1105 ; MD1.10@4503.56,1553.76 4503.56,1509.47 4546.5,1466.53 R4.2@4546.5,1448.5 4546.5,1443.5 4578.47,1411.53 ccw(c4727.01,1560.06) 4727.01,1350
  Bottom Layer w20: J26.1@3750,700 J26.2@3850,700 4000,700 4200,900 4988.06,900 5035,946.94 J6.5@5035,1100 TP10.1@5170,1100 J18.1@5395,1100
CH_P: J6.4 MD1.9 R4.1 TP19.1 | length 901.6
  Top Layer w30: TP19.1@4350,1675 4349.34,1558.09 4353.61,1553.72 4354.13,1553.2 cw(c4354.13,1490.16) 4398.7,1534.73 4486.95,1446.48 4486.95,1431.1 4526.36,1391.69 ccw(c4723.58,1588.91) 4723.58,1310 cw(c4723.58,1210) 4794.29,1280.71 4906.72,1168.28 cw(c4838.43,1100) J6.4@4935,1100
CL_N: J18.5 J25.2 MD1.12 R9.2 TP26.1 | length 2716.5
  Top Layer w30: MD1.12@4950,1550.2 TP26.1@4950,1675 ; MD1.12@4954.13,1553.2 4973.03,1534.29 ccw(c5043.74,1605) 5043.74,1505 5390.15,1505 cw(c5390.15,1405) 5460.86,1475.71 5782.68,1153.89 cw(c5728.79,1100) J18.5@5805,1100
  Bottom Layer w30: J25.2@4450,700 5145,700 5345,900 5537.01,900 5647.01,1010 5759,1010 5805,1056 J18.5@5805,1100
CL_P: J18.4 MD1.11 R9.1 TP25.1 | length 1243.4
  Top Layer w30: MD1.11@4800,1550.2 TP25.1@4800,1675 ; MD1.11@4804.13,1553.2 4863.03,1494.29 ccw(c4933.74,1565) 4933.74,1465 5018.32,1465 5019,1464.32 5043.74,1464.32 5043.74,1464.22 5056.25,1464.22 5057.03,1465 5357.01,1465 cw(c5357.01,1325) 5456.01,1423.99 5675.71,1204.29 cw(c5605,1133.58) 5705,1133.58 J18.4@5705,1100
CLK: J17.17 J19.20 | length 802
  Top Layer w10: J19.20@800,1000 850,950 850,835 926.41,758.59 926.41,475.97 1050,352.38 J17.17@1050,301.52
DGND: J17.1 J19.9 J19.12 | length 760.6
  Bottom Layer w30: J17.1@250,301.52 250,708.77 400,858.77 J19.9@400,900 J19.12@500,900
HS_N: J15.1 MD1.17 | length 3462
  Top Layer w15: MD1.17@4954.13,3202.8 4891.63,3265.3 4891.63,3276.09 4900.54,3285 5949.64,3285 6190,3044.64 6190,1140 J15.1@6150,1100
HS_P: J15.2 MD1.18 | length 3542.8
  Top Layer w15: MD1.18@4804.13,3202.8 4866.63,3265.3 4866.63,3286.44 4890.19,3310 5960,3310 6215,3055 6215,1135 J15.2@6250,1100
HV_GND: C1.2 C2.2 C3.2 C4.2 MD1.13 MD1.14 MD1.27 MD1.28 T2.1
  other v1: 508,1586 588,1586 668,1586 748,1586 828,1586 908,1586 988,1586 1068,1586 1148,1586 1228,1586 1308,1586 1388,1586 1468,1586 1548,1586 1628,1586 1708,1586 1788,1586 1868,1586 1948,1586 468,1666 548,1666 628,1666 708,1666 788,1666 868,1666 948,1666 1028,1666 1108,1666 1188,1666 1268,1666 1348,1666 1428,1666 1508,1666 1588,1666 1668,1666 1748,1666 1828,1666 1988,1666 2068,1666 2148,1666 108,1746 188,1746 428,1746 508,1746 588,1746 668,1746 748,1746 828,1746 908,1746 988,1746 1068,1746 1148,1746 1228,1746 1308,1746 1388,1746 1468,1746 1548,1746 1628,1746 1708,1746 1788,1746 2028,1746 2108,1746 2188,1746 148,1826 228,1826 308,1826 388,1826 468,1826 548,1826 628,1826 708,1826 788,1826 868,1826 948,1826 1028,1826 1108,1826 1188,1826 1268,1826 1348,1826 1428,1826 1508,1826 1588,1826 1668,1826 1748,1826 1828,1826 1988,1826 2068,1826 2148,1826 2228,1826 2308,1826 108,1906 188,1906 268,1906 348,1906 428,1906 508,1906 588,1906 668,1906 748,1906 828,1906 908,1906 988,1906 1068,1906 1148,1906 1228,1906 1308,1906 1388,1906 1468,1906 1548,1906 1628,1906 1708,1906 1788,1906 1868,1906 1948,1906 2028,1906 2108,1906 2268,1906 2348,1906 148,1986 228,1986 308,1986 388,1986 468,1986 548,1986 628,1986 708,1986 788,1986 868,1986 948,1986 1028,1986 1108,1986 1188,1986 1268,1986 1348,1986 1428,1986 1508,1986 1588,1986 1668,1986 1748,1986 1828,1986 1908,1986 1988,1986 2068,1986 2308,1986 2388,1986 3068,1986 3148,1986 3228,1986 3308,1986 3388,1986 3468,1986 3548,1986 3628,1986 3708,1986 3788,1986 3868,1986 3948,1986 4028,1986 4108,1986 4188,1986 4268,1986 4348,1986 4428,1986 4508,1986 108,2066 188,2066 268,2066 348,2066 428,2066 508,2066 588,2066 668,2066 748,2066 828,2066 908,2066 988,2066 1068,2066 1148,2066 1228,2066 1308,2066 1388,2066 1468,2066 1628,2066 1708,2066 1788,2066 1868,2066 1948,2066 2028,2066 2108,2066 2268,2066 2348,2066 3108,2066 3188,2066 3268,2066 3348,2066 3428,2066 3508,2066 3588,2066 3668,2066 3748,2066 3828,2066 3908,2066 3988,2066 4068,2066 4148,2066 4228,2066 4308,2066 4388,2066 4468,2066 148,2146 228,2146 308,2146 388,2146 468,2146 548,2146 628,2146 1348,2146 1428,2146 1508,2146 1588,2146 1668,2146 1748,2146 1828,2146 1908,2146 1988,2146 2068,2146 2148,2146 2228,2146 2308,2146 2388,2146 108,2226 188,2226 268,2226 348,2226 428,2226 508,2226 1388,2226 1468,2226 1548,2226 1628,2226 1708,2226 1788,2226 2108,2226 2188,2226 2268,2226 2348,2226 148,2306 228,2306 308,2306 388,2306 468,2306 548,2306 108,2386 188,2386 268,2386 348,2386 148,2466 228,2466 308,2466 548,2466 108,2546 188,2546 268,2546 348,2546 428,2546 508,2546 148,2626 228,2626 308,2626 388,2626 468,2626 548,2626 108,2706 188,2706 268,2706 348,2706 428,2706 508,2706 148,2786 228,2786 308,2786 388,2786 468,2786 548,2786 108,2866 188,2866 268,2866 348,2866 428,2866 508,2866 148,2946 228,2946 308,2946 388,2946 468,2946 548,2946 108,3026 188,3026 268,3026 348,3026 428,3026 508,3026 148,3106 228,3106 308,3106 388,3106 468,3106 548,3106 108,3186 188,3186 268,3186 348,3186 428,3186 508,3186 148,3266 228,3266 308,3266 388,3266 468,3266 548,3266 108,3346 188,3346 268,3346 348,3346 428,3346 508,3346 148,3426 228,3426 308,3426 388,3426 468,3426 548,3426 108,3506 188,3506 268,3506 348,3506 148,3586 228,3586 308,3586 548,3586 108,3666 188,3666 268,3666 348,3666 428,3666 508,3666 148,3746 228,3746 308,3746 388,3746 468,3746 548,3746 108,3826 188,3826 268,3826 348,3826 428,3826 508,3826 148,3906 228,3906 308,3906 388,3906 468,3906 548,3906 108,3986 188,3986 268,3986 348,3986 428,3986 508,3986 148,4066 228,4066 308,4066 388,4066 468,4066 548,4066 108,4146 188,4146 268,4146 348,4146 428,4146 508,4146
  other v2: 120,4470 160,4470 200,4470 500,4470 540,4470 580,4470 120,4510 580,4510 120,4550 580,4550 125,4985 165,4985 205,4985 245,4985 285,4985 325,4985 375,4985 415,4985 455,4985 495,4985 535,4985 575,4985 125,5025 165,5025 205,5025 245,5025 285,5025 325,5025 375,5025 415,5025 455,5025 495,5025 535,5025 575,5025 125,5065 165,5065 205,5065 245,5065 285,5065 325,5065 375,5065 415,5065 455,5065 495,5065 535,5065 575,5065 125,5105 165,5105 205,5105 245,5105 285,5105 325,5105 375,5105 415,5105 455,5105 495,5105 535,5105 575,5105
Ia_N: J16.5 J22.20 | length 4112.2
  Top Layer w15: J16.5@6250,3975 6300,3925 6300,3850 6800,3350 6800,354.64 6681.04,235.69 6635.69,235.69 J22.20@6600,200
Ia_P: J16.6 J22.19 | length 3962
  Top Layer w15: J16.6@6250,3875 6250,3864.64 6279.11,3835.53 6775,3339.64 6775,365 6670.69,260.69 6639.31,260.69 J22.19@6600,300
Ib_N: J16.3 J22.18 | length 4106.4
  Top Layer w15: J16.3@6150,3975 6200,3925 6200,3822.05 6717.68,3304.37 6725,3297.05 6725,520.35 6552.8,348.15 6552.8,320.14 6552.38,319.72 6552.38,252.38 J22.18@6500,200
Ib_P: J16.4 J22.17 | length 3885.7
  Top Layer w15: J16.4@6150,3875 6175,3850 6175,3811.69 6700,3286.69 6700,530.7 6527.8,358.5 6527.8,330.49 6527.38,330.08 6527.38,327.38 J22.17@6500,300
Ic_N: J16.1 J22.16 | length 4127.1
  Top Layer w15: J16.1@6050,3975 6100,3925 6100,3820 6650,3270 6650,575.33 6447.62,372.95 6447.62,247.62 J22.16@6400,200
Ic_P: J16.2 J22.15 | length 3908.1
  Top Layer w15: J16.2@6050,3875 6075,3850 6075,3809.64 6625,3259.64 6625,585.69 6439.31,400 6422.62,383.31 J22.15@6422.62,313.34 ; J22.15@6400,300 6404.34,295.66 J22.15@6422.62,295.66
In+_A: J17.9 J19.15 | length 619.2
  Top Layer w10: J19.15@600,900 600,860 650,810 J17.9@650,301.52
In+_B: J17.12 J19.14 | length 860.6
  Top Layer w10: J19.14@600,1000 650,950 650,850 700,800 700,251.52 J17.12@750,201.52
In+_C: J17.16 J19.16 | length 1002
  Top Layer w10: J19.16@700,1100 750,1050 750,865 875,740 875,448.78 900,423.78 900,251.52 J17.16@950,201.52
In-_A: J17.11 J19.13 | length 889.7
  Top Layer w10: J17.11@750,301.52 v4(750,760)
  Bottom Layer w10: J19.13@600,1100 650,1050 650,975 675,950 724.66,950 750,924.66 v4(750,760)
In-_B: J17.13 J19.18 | length 660.6
  Top Layer w10: J19.18@700,900 700,880 850,730 J17.13@850,301.52
In-_C: J17.14 J19.17 | length 948.9
  Top Layer w10: v4(800,715) 800,251.52 J17.14@850,201.52
  Bottom Layer w10: J19.17@700,1000 716.81,1000 766.81,950 830,950 850,930 850,765 v4(800,715)
nCS: J17.18 J19.24 | length 802
  Top Layer w10: J19.24@900,900 900,818.36 955,763.36 955,494.66 1100,349.66 1100,251.52 J17.18@1050,201.52
NetH1_1: H1.1 T6.1
  other v2: 5570,4470 5610,4470 5650,4470 5950,4470 5990,4470 6030,4470 5570,4510 6030,4510 5570,4550 6030,4550 6188,4866 6268,4866 6348,4866 6428,4866 6508,4866 6588,4866 6668,4866 6228,4946 6308,4946 6388,4946 6468,4946 6548,4946 6628,4946 6708,4946 5575,4985 5615,4985 5655,4985 5695,4985 5735,4985 5775,4985 5825,4985 5865,4985 5905,4985 5945,4985 5985,4985 6025,4985 5575,5025 5615,5025 5655,5025 5695,5025 5735,5025 5775,5025 5825,5025 5865,5025 5905,5025 5945,5025 5985,5025 6025,5025 6188,5026 6268,5026 6348,5026 6428,5026 6508,5026 6588,5026 6668,5026 5575,5065 5615,5065 5655,5065 5695,5065 5735,5065 5775,5065 5825,5065 5865,5065 5905,5065 5945,5065 5985,5065 6025,5065 5575,5105 5615,5105 5655,5105 5695,5105 5735,5105 5775,5105 5825,5105 5865,5105 5905,5105 5945,5105 5985,5105 6025,5105
NetJ5_1: J5.1 TP7.1 | length 140
  Top Layer w15: TP7.1@2650,3735 J5.1@2650,3875
NetJ5_2: J5.2 R3.2 | length 353.1
  Top Layer w12: R3.2@2329.62,3896.09 2401.09,3896.09 2435,3930 2579.41,3930 2624.41,3975 J5.2@2650,3975
NetJ5_3: J5.3 R10.2 TP8.1 | length 215.6
  Top Layer w15: R10.2@2476.5,3740 2545,3740 TP8.1@2550,3735 J5.3@2550,3875
NetJ5_4: J5.4 R3.1 | length 227.2
  Top Layer w12: R3.1@2331.96,3952.81 2527.81,3952.81 J5.4@2550,3975
NetJ8_1: J8.1 TP11.1 | length 146
  Top Layer w15: J8.1@3850,3875 3850,3736.11 TP11.1@3855,3731.11
NetJ8_2: J8.2 R5.2 | length 353.1
  Top Layer w12: R5.2@3529.62,3896.09 3602.6,3896.09 3631.52,3925 3775,3925 3825,3975 J8.2@3850,3975
NetJ8_3: J8.3 R11.2 TP12.1 | length 224.8
  Top Layer w15: TP12.1@3750,3728.52 J8.3@3750,3875
  Top Layer w25: R11.2@3675,3730.95 3747.56,3730.95 TP12.1@3750,3728.52 TP12.1@3751.62,3726.9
